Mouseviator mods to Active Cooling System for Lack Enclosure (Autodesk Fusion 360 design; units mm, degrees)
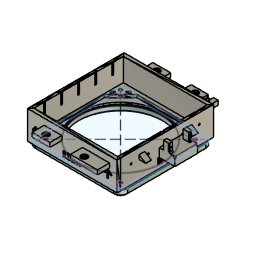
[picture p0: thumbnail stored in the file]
parameter "hole_diameter" = 4.005
parameter "fan_hole_d" = 116.606
base_mesh_feature "Base Mesh Feature"
step "Body->Comp"
convert_mesh "Convert Mesh" bodies "Main Support structure (not definitive)"
delete_face "DeleteFace1"
delete_face "DeleteFace2"
delete_face "DeleteFace3"
delete_face "DeleteFace4"
delete_face "DeleteFace5"
delete_face "DeleteFace6"
delete_face "DeleteFace7"
delete_face "DeleteFace8"
delete_face "DeleteFace9"
delete_face "DeleteFace10"
delete_face "DeleteFace11"
delete_face "DeleteFace12"
delete_face "DeleteFace13"
delete_face "DeleteFace14"
delete_face "DeleteFace15"
delete_face "DeleteFace16"
delete_face "DeleteFace17"
delete_face "DeleteFace18"
delete_face "DeleteFace19"
delete_face "DeleteFace20"
delete_face "DeleteFace21"
delete_face "DeleteFace22"
delete_face "DeleteFace23"
delete_face "DeleteFace24"
sketch "Sketch1" plane through (0, 0, 30) normal (0, 0, -1) x axis (1, 0, 0)
  line L1 (40.489, -63.007) -> (-85.511, -63.007)
  line L2 (40.489, 67.992) -> (40.489, -63.007)
  line L3 (-85.511, 67.992) -> (40.489, 67.992)
  line L4 (-85.511, -63.007) -> (-85.511, 67.992)
  line L5 (37.491, 64.995) -> (37.491, 41.993)
  line L6 (-82.514, 64.995) -> (37.491, 64.995)
  line L7 (-82.514, 41.993) -> (-82.514, 64.995)
  line L8 (-82.514, -24.007) -> (-82.514, 41.993)
  line L9 (-82.514, -55.01) -> (-82.514, -24.007)
  line L10 (37.491, -55.01) -> (-82.514, -55.01)
  line L11 (37.491, -32.007) -> (37.491, -55.01)
  line L12 (37.491, 41.993) -> (37.491, -32.007)
  line L13 (30.025, -44.308) -> (27.34, -45.706)
  line L14 (32.672, -46.117) -> (30.025, -44.308)
  line L15 (32.635, -49.323) -> (32.672, -46.117)
  line L16 (29.95, -50.72) -> (32.635, -49.323)
  line L17 (27.302, -48.912) -> (29.95, -50.72)
  line L18 (27.34, -45.706) -> (27.302, -48.912)
  line L19 (-72.365, 55.677) -> (-72.328, 58.883)
  line L20 (-75.05, 54.28) -> (-72.365, 55.677)
  line L21 (-77.698, 56.088) -> (-75.05, 54.28)
  line L22 (-77.66, 59.295) -> (-77.698, 56.088)
  line L23 (-74.975, 60.692) -> (-77.66, 59.295)
  line L24 (-72.328, 58.883) -> (-74.975, 60.692)
  line L25 (-77.698, -48.912) -> (-75.05, -50.72)
  line L26 (-77.66, -45.706) -> (-77.698, -48.912)
  line L27 (-74.975, -44.308) -> (-77.66, -45.706)
  line L28 (-72.328, -46.117) -> (-74.975, -44.308)
  line L29 (-72.365, -49.323) -> (-72.328, -46.117)
  line L30 (-75.05, -50.72) -> (-72.365, -49.323)
  line L31 (27.34, 59.295) -> (27.302, 56.088)
  line L32 (30.025, 60.692) -> (27.34, 59.295)
  line L33 (32.672, 58.883) -> (30.025, 60.692)
  line L34 (32.635, 55.677) -> (32.672, 58.883)
  line L35 (29.95, 54.28) -> (32.635, 55.677)
  line L36 (27.302, 56.088) -> (29.95, 54.28)
  line L37 (37.491, -55.01) -> (-82.514, 64.995)
  line L38 (37.491, 64.995) -> (-82.514, -55.01)
  line L39 (32.491, 69.995) -> (-77.514, 69.995)
  line L40 (42.491, -50.01) -> (42.491, 59.995)
  line L41 (-77.514, -60.01) -> (32.491, -60.01)
  line L42 (-87.514, 59.995) -> (-87.514, -50.01)
  line L43 (-75.05, 54.28) -> (-74.975, 60.692)
  line L44 (-77.698, 56.088) -> (-72.328, 58.883)
  line L45 (-72.365, 55.677) -> (-77.66, 59.295)
  arc A1 centre (-77.514, 59.995) radius 10 clockwise from (-87.514, 59.995) to (-77.514, 69.995)
  arc A2 centre (32.491, 59.995) radius 10 clockwise from (32.491, 69.995) to (42.491, 59.995)
  arc A3 centre (32.491, -50.01) radius 10 clockwise from (42.491, -50.01) to (32.491, -60.01)
  arc A4 centre (-77.514, -50.01) radius 10 clockwise from (-77.514, -60.01) to (-87.514, -50.01)
  circle C1 centre (-22.5115, 4.9925) radius 58.303
  circle C2 centre (-75.0125, 57.486) radius 2.0025
  circle C3 centre (29.9865, 57.486) radius 2.0025
  circle C4 centre (-75.0125, -47.513) radius 2.0025
  circle C5 centre (29.9865, -47.513) radius 2.0025
  point P8 (-82.514, 64.995)
  point P38 (-82.514, 64.995)
  point P12 (37.491, -55.01)
  point P39 (37.491, -55.01)
  point P11 (-82.514, -55.01)
  point P40 (-82.514, -55.01)
  point P7 (37.491, 64.995)
  point P41 (37.491, 64.995)
  point P57 (-22.5115, 4.9925)
  point P25 (-74.975, 60.692)
  point P58 (-74.975, 60.692)
  point P22 (-75.05, 54.28)
  point P59 (-75.05, 54.28)
  point P20 (-72.328, 58.883)
  point P60 (-72.328, 58.883)
  point P23 (-77.698, 56.088)
  point P61 (-77.698, 56.088)
  point P24 (-77.66, 59.295)
  point P62 (-77.66, 59.295)
  point P21 (-72.365, 55.677)
  point P63 (-72.365, 55.677)
  point P64 (-75.0125, 57.486)
  coincident P8 P38
  coincident P12 P39
  coincident P11 P40
  coincident P7 P41
  tangent L39 A1
  tangent L42 A1
  tangent L39 A2
  tangent L40 A2
  equal A1 A2
  tangent L40 A3
  tangent L41 A3
  equal A1 A3
  tangent L42 A4
  tangent L41 A4
  equal A1 A4
  midpoint L37 P57
  coincident P25 P58
  coincident P22 P59
  coincident P20 P60
  coincident P23 P61
  coincident P24 P62
  coincident P21 P63
  midpoint L43 P64
  dimension "d2" radius A1 = 10
  dimension "d9" diameter C1 = 116.606 (= "fan_hole_d")
  dimension "d10" diameter C2 = 4.005 (= "hole_diameter")
  dimension "d13" R-Pattern1-uDistance = 104.999
  dimension "d14" R-Pattern1-vDistance = -104.999
extrude "Extrude1" new body sketch "Sketch1" profile of L2 L3 L4 L5 L6 L7 L8 L9 L10 L11 L12 L13 L14 L15 L16 L17 L18 L19 L20 L21 L22 L23 L24 L25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 along normal blind 8
chamfer "Chamfer1" distance 2 distance 2
extrude "Extrude2" cut sketch "Sketch1" profile of C2 C3 C4 C5 no distance stored
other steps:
create_component "CreateComponent1"
copy_paste_meshes "CutPasteMeshes"
create_component "CreateComponent2"
named bodies: "Main Support structure (not definitive)", "Main Support structure (not definitive) (1)"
